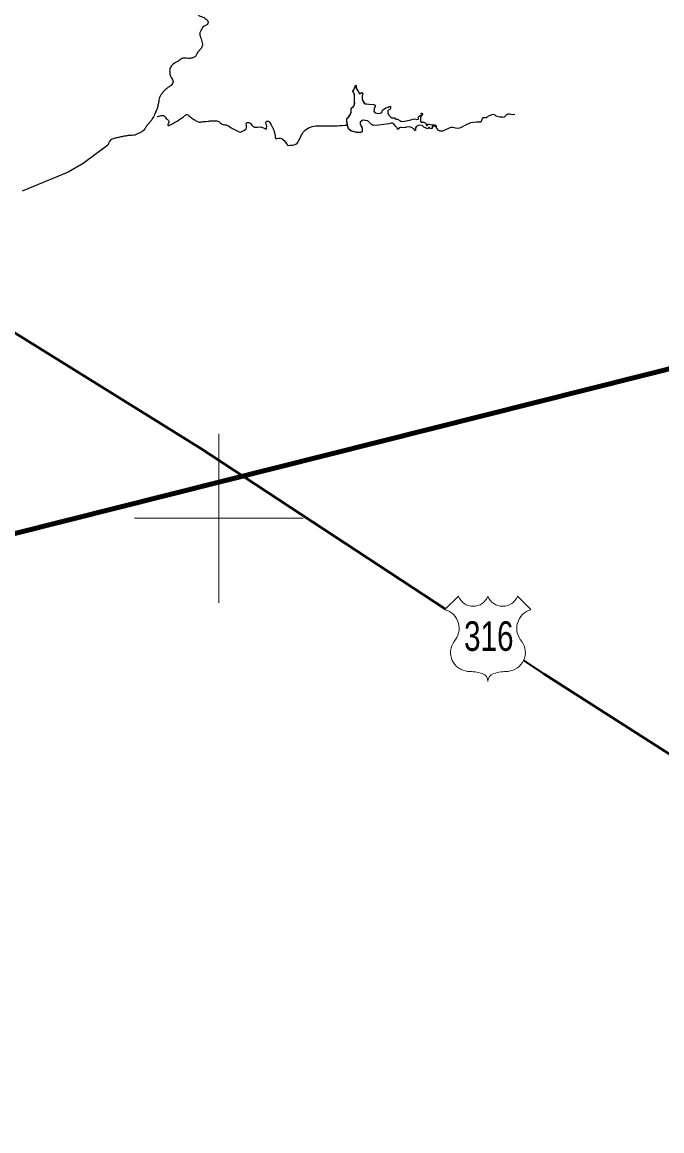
# Model space of a CAD drawing. Extents: x -1643653 to 4543381, y 1624270 to 13878484.
# Drawn here: x 672672 to 680246, y 8967746 to 8980875 of the extents above; entities that cross this region are included whole.
import ezdxf
from ezdxf.enums import TextEntityAlignment as Align

# ---------------------------------------------------------------- set-up
doc = ezdxf.new("R2010")
doc.units = 0
doc.header["$LTSCALE"] = 200
for name, color, linetype, lineweight in [('12', 7, 'Continuous', 25), ('2', 7, 'Continuous', 13), ('24', 7, 'Continuous', 25), ('26', 7, 'Continuous', 106), ('28', 7, 'Continuous', 53), ('48', 7, 'Continuous', 25), ('60', 7, 'Continuous', 13), ('9', 7, 'Continuous', 90)]:
    doc.layers.add(name, color=color, linetype=linetype, lineweight=lineweight)

msp = doc.modelspace()

# ---------------------------------------------------------------- linework, layer by layer
at = {"layer": '12', "lineweight": 40}
for points in [[(664631.3, 8982143.9), (674788, 8975827.4), (677683.8, 8973924.7)], [(678613, 8973314.2), (678848.5, 8973159.5), (686496, 8968269.5), (688991.1, 8966516.2), (690142.8, 8964774.6), (690545.4, 8964311.7), (690844.1, 8964097.1), (691108, 8963953.4), (691274.5, 8963904.3)]]:
    msp.add_lwpolyline(points, dxfattribs=at)
at = {"layer": '2'}
for p, q in [((675000, 8974000), (675000, 8976000)), ((674000, 8975000), (676000, 8975000))]:
    msp.add_line(p, q, dxfattribs=at)
at = {"layer": '24'}
for points in [[(676735.1, 8979710.2), (676716.5, 8979713.3), (676699.8, 8979711.5), (676685.3, 8979701), (676673.4, 8979689.2), (676673.4, 8979670.8), (676681.3, 8979649.7), (676691.9, 8979635.3), (676697.1, 8979616.9), (676698.5, 8979598.5), (676695.8, 8979578.7), (676691.9, 8979570.9), (676670.8, 8979568.2), (676655, 8979568.2), (676631.3, 8979569.5), (676591.8, 8979578.7), (676557.6, 8979590.6), (676537.4, 8979611.3), (676526.2, 8979640.9), (676516.8, 8979711.5), (676518.1, 8979733.9), (676535.2, 8979749.7), (676548.4, 8979769.1), (676562.9, 8979792.8), (676566.8, 8979819.1), (676566.8, 8979833.5), (676568.2, 8979848), (676574.8, 8979859.8), (676593.2, 8979878.2), (676607.7, 8979899.2), (676607.7, 8979926.8), (676606.3, 8979975.5), (676605, 8980003.1), (676605, 8980020.2), (676598.4, 8980038.6), (676585.3, 8980057), (676599.8, 8980074.1), (676609, 8980103), (676616.9, 8980114.8), (676618.2, 8980128), (676626.1, 8980125.4), (676627.4, 8980108.3), (676629.1, 8980090.7), (676636.6, 8980075.4), (676656.4, 8980042.5), (676661.6, 8980030.7), (676673.5, 8980032), (676685.3, 8980039.9), (676695.9, 8980041.2), (676705.1, 8980028.1), (676697.2, 8980008.4), (676698.5, 8979987.3), (676698.5, 8979967.6), (676706.4, 8979943.9), (676716.9, 8979921.6), (676734, 8979909.8), (676749.8, 8979906.6)], [(677114.5, 8979604.9), (677115.1, 8979612.9), (677109.9, 8979626.4), (677088.3, 8979647.8), (677071.6, 8979672.7), (677058.5, 8979678.1), (677042.4, 8979678.5), (677011.8, 8979672.8), (676893.9, 8979653.4), (676833.5, 8979650.9), (676806.7, 8979663.1), (676786.2, 8979685), (676764.8, 8979705), (676734.4, 8979710.3), (676704, 8979712.9), (676679.2, 8979696.2), (676672.1, 8979684), (676673.9, 8979668.5), (676687.2, 8979642), (676697.5, 8979614.2), (676697.2, 8979584.4), (676691.5, 8979570.5), (676677.1, 8979567.8), (676646.6, 8979568.3), (676587.6, 8979579.8), (676559.2, 8979589.7), (676539.3, 8979608.2), (676527.7, 8979635), (676521.6, 8979666.9), (676517.9, 8979700.7), (676517.3, 8979732.2), (676538.4, 8979753.2), (676554.7, 8979778.5), (676566, 8979805.8), (676566.8, 8979835.9), (676569.1, 8979850.7), (676577.5, 8979863.1), (676599, 8979884.4), (676607, 8979897.2), (676609, 8979911.7), (676606.8, 8979942.2), (676605, 8980001.9), (676602.5, 8980031.5), (676585.3, 8980056.7), (676602.9, 8980080.8), (676605.9, 8980095.8), (676613.4, 8980108.1), (676616.7, 8980123.8), (676619.7, 8980128.2), (676626.8, 8980124.6), (676628.2, 8980093.8), (676656.8, 8980041), (676659.3, 8980033.3), (676664.7, 8980029.9), (676679.1, 8980035.7), (676692.6, 8980041.7), (676704.2, 8980032.5), (676701.9, 8980018), (676696.6, 8980004.1), (676698.3, 8979973.9), (676705.9, 8979945.2), (676719.6, 8979918.7), (676732.3, 8979910.4), (676746.8, 8979906.9), (676777, 8979904.4), (676836.4, 8979899), (676850.4, 8979891.1), (676851.1, 8979877.8), (676838.2, 8979849.8), (676834.1, 8979820.2), (676843.5, 8979808.4), (676856.4, 8979800.3), (676885, 8979792.4), (676915.7, 8979796.6), (676928.5, 8979805.1), (676935.4, 8979818.4), (676939.9, 8979833), (676950.8, 8979842.2), (676975.9, 8979858.9), (677004.3, 8979868.5), (677017.3, 8979875.3), (677031.4, 8979875.7), (677031.6, 8979859.5), (677027.7, 8979845.7), (677003.2, 8979827.9), (677002, 8979798), (677015.4, 8979771.4), (677036.3, 8979750.6), (677048.8, 8979742.4), (677064.8, 8979742.1), (677080.2, 8979742.2), (677089.3, 8979731.5), (677101.6, 8979725.9), (677117.8, 8979725.7), (677142.9, 8979708.9), (677155.6, 8979701.6)], [(677155.6, 8979701.6), (677170.5, 8979699.7), (677200.8, 8979701.8), (677259.5, 8979713.3), (677316.6, 8979731.3), (677344.6, 8979722.9), (677361.8, 8979724.7), (677366.5, 8979727.8), (677363.7, 8979734.2), (677362.3, 8979749.5), (677372.1, 8979760.8), (677383.9, 8979769.2), (677397.3, 8979775.5), (677399.5, 8979782.8), (677396.3, 8979789.8), (677396.1, 8979795.5), (677404.7, 8979796.3), (677412.1, 8979791.8), (677413.3, 8979785.2), (677403.4, 8979772.9), (677389.9, 8979746.9), (677386.7, 8979716.6), (677386.8, 8979701.8), (677397.3, 8979692.6), (677427.6, 8979689.4), (677443, 8979683.4), (677453.8, 8979672.6), (677454.6, 8979657.8), (677461.1, 8979653.1), (677469.3, 8979653.2), (677476.8, 8979665.5), (677489, 8979668.4), (677523.5, 8979658.6), (677553.6, 8979659.1), (677567.5, 8979655.6), (677575.8, 8979641.4), (677575.5, 8979634.3), (677568.5, 8979633), (677556.3, 8979641.9), (677526.7, 8979644.7), (677525.7, 8979637.3), (677532.1, 8979633.1), (677533.9, 8979626.8), (677527.9, 8979622.2), (677518.5, 8979611.5), (677503.8, 8979615.5), (677494.3, 8979626.8), (677486.9, 8979625.8), (677482.3, 8979619.9), (677469.5, 8979612.2), (677457.2, 8979620), (677429.7, 8979631.4), (677407.4, 8979651.1), (677377.8, 8979653.9), (677362.2, 8979653.1), (677350.3, 8979644.9), (677337.8, 8979636.6), (677328.8, 8979624.6), (677327.9, 8979593.7), (677325.9, 8979591.1), (677321.2, 8979595.4), (677308.1, 8979611.2), (677282.1, 8979626.2), (677253.3, 8979633.9), (677223.3, 8979632.2), (677209.6, 8979626.2), (677194.8, 8979625.1), (677165.1, 8979628.9), (677150.2, 8979628.9), (677136.1, 8979624), (677129.1, 8979610.6), (677115.2, 8979605.2)], [(677574.7, 8979633.6), (677579.2, 8979618), (677589.5, 8979605.1), (677602, 8979594.2), (677617.3, 8979588.8), (677650, 8979586.2), (677679.8, 8979600), (677740, 8979626.6), (677754.9, 8979633.3), (677770.9, 8979630.5), (677803, 8979623.7), (677834.8, 8979618.1), (677866.2, 8979629.4), (677923.4, 8979661), (677983.4, 8979687.5), (678048.2, 8979693.8), (678080.8, 8979695), (678098.1, 8979695.7), (678110.9, 8979703.2), (678121.9, 8979734.2), (678131.9, 8979746.2), (678148.5, 8979745), (678164.7, 8979744.1), (678179, 8979752.6), (678205.7, 8979770.8), (678236.6, 8979781.6), (678253.3, 8979785.3), (678266.6, 8979777.3), (678279, 8979766.4), (678294.1, 8979760.1), (678326.5, 8979755.5), (678358.9, 8979753.7), (678375, 8979750.2), (678382.5, 8979752.8), (678387.1, 8979759.7), (678409.9, 8979782.6), (678425.2, 8979788.5), (678441.7, 8979789.2), (678473.9, 8979781.9), (678506.3, 8979785.6)], [(675087.2, 8979659.3), (675095, 8979655.6), (675114.1, 8979645.4), (675146.7, 8979624.2), (675208.2, 8979591.3), (675240.7, 8979575.2), (675257.5, 8979573.3), (675274.6, 8979579), (675305.8, 8979595.8), (675319.4, 8979607.2), (675327.3, 8979622.7), (675327.6, 8979658.2), (675323.6, 8979674.8), (675328.6, 8979681.6), (675337.3, 8979685.4), (675354.3, 8979685.1), (675371.1, 8979678.1), (675396.3, 8979653.2), (675408.5, 8979640.4), (675424, 8979631.9), (675459.2, 8979632.5), (675494.4, 8979633.6), (675528, 8979622.3), (675560.4, 8979608.1), (675566.2, 8979614.1), (675565.7, 8979622.9), (675567.7, 8979640.6), (675564.3, 8979657.6), (675557.1, 8979673.7), (675557, 8979691.4), (675570.5, 8979702.5), (675587.8, 8979702.3), (675600.7, 8979690.3), (675618.7, 8979659.8), (675651.8, 8979597.5), (675665.5, 8979528.3), (675666.5, 8979510.4), (675673.8, 8979496.2), (675691.8, 8979495.5), (675711.8, 8979499.3), (675729.3, 8979500.5), (675745.4, 8979495.8), (675773.5, 8979473.1), (675814.3, 8979417.8), (675820.2, 8979416.2)], [(673685.8, 8979419.8), (673393.2, 8979201.1), (673214.8, 8979097.3), (672672.1, 8978875.5)]]:
    msp.add_lwpolyline(points, dxfattribs=at)
for points in [[(675088.2, 8981289.5), (675084.6, 8981286.1), (675073.1, 8981281), (675059.7, 8981272.7), (675039.9, 8981265.7), (675019.6, 8981265.6), (674995.4, 8981268.7), (674982, 8981273.1), (674960.3, 8981278.1), (674940.6, 8981276.2), (674934.2, 8981266.7), (674930.4, 8981246.4), (674930.3, 8981233.3), (674939.2, 8981216.9), (674950, 8981194.1), (674950, 8981172.6), (674932.2, 8981151.7), (674910.5, 8981138.4), (674888.2, 8981126.9), (674870.8, 8981114.5), (674849.1, 8981094.2), (674823.7, 8981070.8), (674802, 8981051.2), (674784.8, 8981030.3), (674766.2, 8981002.1), (674758, 8980979.3), (674754.2, 8980961.6), (674762.4, 8980950.3), (674795.5, 8980943.4), (674824.7, 8980928.9), (674855.4, 8980911.6), (674866.2, 8980896.4), (674876.3, 8980876.2), (674874.2, 8980857.5), (674852.5, 8980838.7), (674834.8, 8980830.4), (674816.2, 8980826.5), (674798.8, 8980797.3), (674785.8, 8980771.4), (674778.7, 8980757.7), (674774.3, 8980746.3), (674774.3, 8980730.6), (674779.7, 8980710.9), (674789.6, 8980677.2), (674799.5, 8980647.8), (674809.4, 8980612.7), (674805.2, 8980583.2), (674774.2, 8980544.7), (674750.3, 8980520.8), (674739, 8980494.1), (674719.4, 8980460.5), (674681.4, 8980447.8), (674633.7, 8980443.5), (674600.1, 8980450.4), (674572.5, 8980450.3), (674553, 8980439), (674525.2, 8980417.8), (674494.6, 8980402.3), (674473.2, 8980385.5), (674449, 8980368.7), (674429.1, 8980349.2), (674417.7, 8980318.3), (674418.2, 8980300.5), (674418.2, 8980271.1), (674421.1, 8980248.6), (674435.4, 8980221.9), (674452.6, 8980193.8), (674461.2, 8980171.3), (674452.6, 8980146.1), (674437, 8980126.5), (674405.6, 8980106.4), (674374.2, 8980081.3), (674342.8, 8980050.5), (674311.5, 8980012.7), (674298.6, 8979983.2), (674290.1, 8979952.4), (674283, 8979903.3), (674270.2, 8979852.8), (674250.5, 8979810.5), (674243.8, 8979793.3), (674225.4, 8979755.1)], [(674269.9, 8979755.2), (674271, 8979755.6), (674281, 8979758.8), (674301.5, 8979764.1), (674322.1, 8979771.7), (674348.5, 8979771.6), (674363.3, 8979753.9), (674372.3, 8979741.2), (674378.3, 8979735)], [(674378.3, 8979735), (674384.3, 8979728.8), (674399.4, 8979716.5), (674413.6, 8979702), (674406.5, 8979679.2), (674395.3, 8979662.6), (674398.5, 8979650.6), (674415.9, 8979653.8), (674449.4, 8979671.4), (674501.4, 8979697.8), (674579.8, 8979752.3), (674601.8, 8979771.3), (674617.6, 8979782), (674634.1, 8979778.8), (674651.9, 8979763), (674669.8, 8979744), (674693.9, 8979732.5), (674719.3, 8979715.9), (674739.1, 8979699.9), (674757.5, 8979693.5), (674779.1, 8979691.4), (674805.7, 8979694.5), (674831.1, 8979699.4), (674872.3, 8979701.7), (674917.4, 8979707.8), (674962.5, 8979706.9), (674989.8, 8979703.6), (675008.2, 8979692.1), (675027.3, 8979672.9), (675045.8, 8979662.6), (675065.5, 8979660.6), (675080.1, 8979660.5), (675087.2, 8979659.3)], [(674225.4, 8979755.1), (674222.2, 8979749.1), (674211.1, 8979728.9), (674193.8, 8979701.7), (674168, 8979673.7), (674143.7, 8979647.1), (674129.5, 8979619.1), (674096.6, 8979574.2), (674050.8, 8979561.7), (674019.3, 8979542.1), (673990.7, 8979533.8), (673947.8, 8979533.8), (673904.9, 8979528.3), (673866.3, 8979522.8), (673814.8, 8979508.9), (673766.2, 8979501.9), (673727.5, 8979486.2), (673707.4, 8979468.8), (673695.9, 8979444.3), (673685.8, 8979419.8)]]:
    msp.add_open_spline(points, degree=3, dxfattribs=at)
msp.add_spline([(675820.2, 8979416.2), (675913.3, 8979430.9), (675996.6, 8979568.1), (676148.5, 8979646.5), (676280.7, 8979646.5), (676520.8, 8979656.2)], degree=3, dxfattribs=at)
at = {"layer": '26'}
for points in [[(655983.7, 8975399.4), (656923, 8974848.7), (657608.5, 8974464.4), (658343, 8973736.5), (658963.6, 8973136.3), (659596.6, 8972485.1), (660330.5, 8971655.5), (660495.7, 8971591.2), (661115.6, 8970863.8), (661404.1, 8970086.9), (661693.8, 8969526.2), (662110.5, 8968901.3), (662312.2, 8968544.4), (662816.6, 8967664.9), (663042.2, 8967040.8), (663203.6, 8966302.6), (663365.3, 8965640.7), (663833.2, 8965053.8), (664099.5, 8964849.2), (664772, 8964426.8), (665496.3, 8964144), (666463.4, 8964000.2), (667623.1, 8964148), (668184.3, 8964285.6), (669317.4, 8964230), (670221.1, 8964150), (671187.7, 8963917.1), (671823.3, 8963711.1), (672497.1, 8963517.5), (673386.9, 8963221.4), (674492.1, 8962733.6), (675125.5, 8962146), (675556, 8961711.9), (676150.3, 8960959.1), (676174.9, 8960921)], [(676174.9, 8960921), (676589.7, 8959851), (677298.5, 8959085), (677905.7, 8958370.4), (678108.1, 8958127.9), (678628.8, 8957871.5), (679175.3, 8957678.5), (679634.1, 8957740.2), (680271.7, 8957890.1), (680680.6, 8958130.1), (682556.7, 8958821.8), (683435.7, 8958881.7), (684580.7, 8958673.6), (685598.3, 8958453.2), (686374.5, 8958348.3), (687212.1, 8957836.1), (687682.2, 8957630.7), (688306.1, 8957615.5), (689591.9, 8957533.9), (690585.7, 8957606.1), (691389.1, 8957793.5), (691759.3, 8957957.3), (692919.9, 8958245), (693572, 8958700.2), (694136.4, 8959422.7), (694705.3, 8960908.2), (694927.7, 8961937.4), (695327.4, 8962800.5), (695494.2, 8963028.7), (696954.2, 8966672.4), (698159, 8968028.2), (699003.1, 8968647.8), (699373.7, 8968875.2), (699705.8, 8969051.9), (700930.8, 8969479.2), (701631.8, 8969565.3), (702395, 8969409.6), (703157, 8969037.7), (703804.2, 8968640.8), (704732, 8968306.3), (704974.2, 8968343.5), (705432.6, 8968328.9), (706400.3, 8968312.2), (707482.9, 8968320.5), (708005.4, 8968381.9), (708718.3, 8968340.8), (709660.3, 8968260.6), (710627.7, 8968180.3), (711187.5, 8968089), (711873, 8967704.7), (712851.5, 8967319.2), (713361.3, 8967393.4), (714238.5, 8967122.7), (715674, 8966506.4), (716373.4, 8966312.8), (717313.4, 8965902), (718673.1, 8965375), (719658.3, 8965140.1)]]:
    msp.add_spline(points, degree=3, dxfattribs=at)
at = {"layer": '28'}
msp.add_spline([(676174.9, 8960921), (676150.3, 8960959.1), (675556, 8961711.9), (675125.5, 8962146), (674492.1, 8962733.6), (673386.9, 8963221.4), (672497.1, 8963517.5), (671823.3, 8963711.1), (671187.7, 8963917.1), (670221.1, 8964150), (669317.4, 8964230), (668184.3, 8964285.6), (667623.1, 8964148), (666463.4, 8964000.2), (665496.3, 8964144), (664772, 8964426.8), (664099.5, 8964849.2), (663833.2, 8965053.8), (663365.3, 8965640.7), (663203.6, 8966302.6), (663042.2, 8967040.8), (662816.6, 8967664.9), (662312.2, 8968544.4), (662110.5, 8968901.3), (661693.8, 8969526.2), (661404.1, 8970086.9), (661115.6, 8970863.8), (660495.7, 8971591.2), (660330.5, 8971655.5), (659596.6, 8972485.1), (658963.6, 8973136.3), (658343, 8973736.5), (657608.5, 8974464.4), (656923, 8974848.7), (655983.7, 8975399.4)], degree=3, dxfattribs=at)
at = {"layer": '48', "lineweight": 13}
for p, q in [((677677.4, 8973917.6), (677837.4, 8974077.5)), ((678536.7, 8974077.5), (678696.6, 8973917.6))]:
    msp.add_line(p, q, dxfattribs=at)
for centre, radius, start, end in [((678012.2, 8974144.5), 187.2, 200.95927, 339.04073), ((678361.8, 8974144.5), 187.2, 200.95927, 339.04073), ((677615.4, 8973695.7), 230.3, 317.5721, 74.36886), ((678758.7, 8973695.7), 230.3, 105.62774, 222.4279), ((677968.9, 8973410.6), 224.7, 144.73733, 264.65778), ((678405.2, 8973410.6), 224.7, 275.34222, 35.26267), ((677946.9, 8972597.1), 589.7, 72.89371, 89.90057), ((678092.7, 8973070.5), 94.4, 357.69345, 72.92955), ((678281.4, 8973070.5), 94.4, 107.07045, 182.30655), ((678427.1, 8972597.1), 589.7, 90.09943, 107.10629)]:
    msp.add_arc(centre, radius, start, end, dxfattribs=at)
at = {"layer": '60', "lineweight": 25}
msp.add_spline([(814781, 9009175.5), (814787.2, 9009173.4), (814796.9, 9009173.4), (814799.4, 9009172.4), (814805.1, 9009174.5), (814805.6, 9009176.5), (814811.7, 9009179.5), (814811.7, 9009179.5), (814801.5, 9009181), (814790.7, 9009181.5), (814784.1, 9009183.1), (814777.4, 9009185.1), (814778.4, 9009175.5)], degree=3, dxfattribs=at)
at = {"layer": '9'}
msp.add_lwpolyline([(658746.8, 8975176), (664691.5, 8973777.5), (669474.2, 8974039.3), (694202.6, 8980257.8)], dxfattribs=at)
msp.add_spline([(637260.6, 8972975.8), (641524.5, 8971056.2), (652526.1, 8965412.7), (653164.3, 8965062.8), (670790.5, 8953770.1), (686194, 8943929.9), (696283.3, 8937647.1)], degree=3, dxfattribs=at)

# ---------------------------------------------------------------- texts
at = {"layer": '48', "width": 0.75}
msp.add_text('316', height=350, dxfattribs=at).set_placement((678197, 8973429.8), align=Align.CENTER)

doc.saveas('drawing.dxf')
